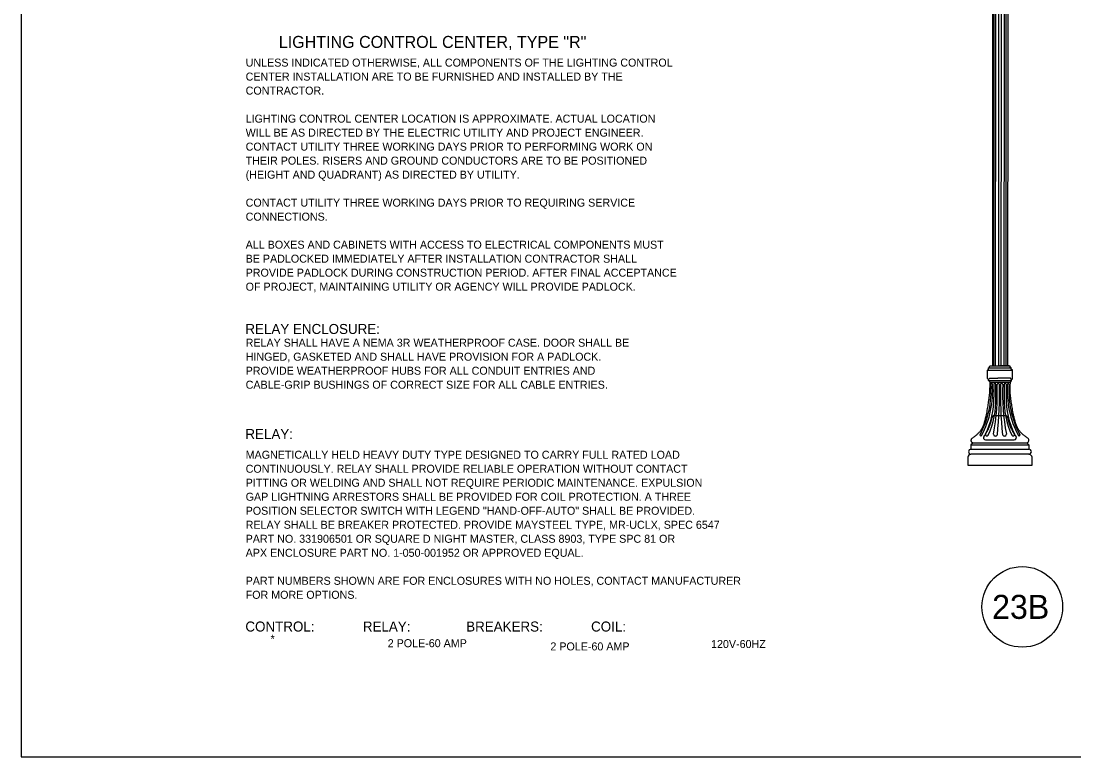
# Model space of a CAD drawing. Extents: x 99968 to 128667, y 90163 to 102182.
# Drawn here: x 120414 to 121992, y 90163 to 91267 of the extents above; entities that cross this region are included whole.
import ezdxf

# ---------------------------------------------------------------- set-up
doc = ezdxf.new("R2010")
doc.units = 0
for name, color, linetype in [('Border Organizer Shape', 7, 'Continuous'), ('Border Prelim Stamp', 7, 'Continuous'), ('RD Standard Plans Active', 7, 'Continuous')]:
    doc.layers.add(name, color=color, linetype=linetype)

msp = doc.modelspace()

# ---------------------------------------------------------------- linework, layer by layer
at = {"layer": 'Border Organizer Shape'}
msp.add_lwpolyline([(120413.5, 90163.3), (123613.2, 90163.3), (123613.2, 92362.9), (120413.5, 92362.9)], close=True, dxfattribs=at)
at = {"layer": 'Border Prelim Stamp'}
msp.add_ellipse((121914.7, 90388.3), major_axis=(-60.5, 0), ratio=0.999984, dxfattribs=at)
at = {"layer": 'RD Standard Plans Active'}
for p, q in [((121870.2, 91544.2), (121869.9, 90749.7)), ((121872.3, 90749.7), (121872.5, 91544.2)), ((121874.8, 90749.7), (121875.1, 91544.2)), ((121879.4, 90749.7), (121879.7, 91544.2)), ((121883.2, 90749.7), (121883.5, 91544.2)), ((121887.8, 90749.7), (121888.1, 91544.2)), ((121890.4, 90749.7), (121890.6, 91544.2)), ((121893, 91544.2), (121892.7, 90749.7)), ((121862.8, 90743.3), (121864.3, 90744.9)), ((121862.8, 90730.8), (121862.8, 90743.3)), ((121862.8, 90743.3), (121899.9, 90743.3)), ((121864.3, 90746.7), (121865.8, 90747.8)), ((121864.3, 90746.7), (121898.1, 90746.7)), ((121864.3, 90744.9), (121864.3, 90746.7)), ((121865.8, 90748.7), (121866.7, 90749.7)), ((121865.8, 90747.8), (121865.8, 90748.7)), ((121866.7, 90749.7), (121895.9, 90749.7)), ((121867.3, 90749.7), (121881.3, 90749.7)), ((121867.9, 90749.7), (121881.3, 90749.7)), ((121867.9, 90749.7), (121894.7, 90749.7)), ((121895.3, 90749.7), (121881.3, 90749.7)), ((121894.7, 90749.7), (121881.3, 90749.7)), ((121896.8, 90748.7), (121895.9, 90749.7)), ((121896.8, 90747.8), (121896.8, 90748.7)), ((121898.3, 90746.5), (121896.8, 90747.8)), ((121898.3, 90744.8), (121898.3, 90746.5)), ((121899.9, 90743.3), (121898.3, 90744.8)), ((121899.9, 90730.4), (121899.9, 90743.3)), ((121864.2, 90729.2), (121862.8, 90730.8)), ((121864.2, 90729.2), (121866.1, 90731.2)), ((121864.2, 90727.6), (121864.2, 90729.2)), ((121866.5, 90725), (121864.2, 90727.6)), ((121864.2, 90727.6), (121899.1, 90727.5)), ((121866.1, 90731.2), (121878, 90731.2)), ((121866.5, 90725), (121896.9, 90725)), ((121897.2, 90731.2), (121878, 90731.2)), ((121896.9, 90725), (121898.7, 90727.1)), ((121898.7, 90729.2), (121897.2, 90731.2)), ((121898.7, 90729.2), (121899.9, 90730.4)), ((121898.7, 90727.1), (121898.7, 90729.2)), ((121871.9, 90722.2), (121872, 90702.5)), ((121874.8, 90722.2), (121874.8, 90702.5)), ((121887.7, 90722.2), (121887.6, 90702.5)), ((121890.5, 90722.2), (121890.5, 90702.5)), ((121890.8, 90674.6), (121871.7, 90674.7)), ((121840.9, 90634.1), (121837.8, 90631.1)), ((121837.8, 90631.1), (121924.7, 90631.1)), ((121837.8, 90631.1), (121837.8, 90624.9)), ((121840.9, 90634.1), (121921.5, 90634.1)), ((121859.5, 90638.9), (121902.6, 90638.9)), ((121888, 90644.5), (121888.2, 90644.5)), ((121921.6, 90634.1), (121924.7, 90631.1)), ((121924.7, 90631.1), (121924.7, 90624.9)), ((121837.8, 90624.9), (121924.7, 90624.9)), ((121924.9, 90617.1), (121837.8, 90617.2)), ((121833, 90612.8), (121833, 90600.8)), ((121833, 90600.8), (121929.5, 90600.7)), ((121929.5, 90600.7), (121929.5, 90612.8))]:
    msp.add_line(p, q, dxfattribs=at)
for centre, radius, start, end in [((121728.1, 90712.3), 139.9, 331.8197, 4.0818), ((121728.1, 90712.3), 142.3, 331.8305, 4.0829), ((121868.8, 90722.2), 1.2, 10.1917, 178.1042), ((121565, 90706.8), 312.3, 349.0347, 2.7955), ((121873.4, 90721.9), 1.47, 12.4479, 167.5521), ((121878.6, 90721.6), 1.74, 17.4755, 167.8586), ((121349.8, 90705.3), 530.8, 353.631, 1.8223), ((122412.7, 90705.3), 530.8, 178.1777, 186.369), ((121883.8, 90721.6), 1.74, 12.1414, 162.5245), ((122197.5, 90706.8), 312.3, 177.2045, 190.9653), ((121889.1, 90721.9), 1.47, 12.4479, 167.5521), ((122034.4, 90712.3), 142.3, 175.9171, 208.1695), ((121893.6, 90722.2), 1.2, 1.8958, 169.8083), ((122034.4, 90712.3), 139.9, 175.9182, 208.1803), ((121755.9, 90699.8), 116.1, 333.1881, 1.3569), ((121754.4, 90697), 120.6, 334.8298, 2.6364), ((122008.1, 90697), 120.6, 177.3636, 205.1702), ((122006.6, 90699.8), 116.1, 178.6431, 206.8119), ((121872.6, 90671.6), 3.13, 105.9115, 168.6516), ((121889.9, 90671.6), 3.13, 11.3484, 73.5955), ((121852.5, 90645.7), 1.2, 149.4961, 332.9376), ((121861.5, 90646.6), 2.18, 159.8381, 335.6064), ((121874.5, 90647.4), 2.93, 180.7471, 344.2322), ((121888, 90647.4), 2.93, 195.7678, 359.2529), ((121900.9, 90646.6), 2.18, 204.3936, 20.1619), ((121910, 90645.7), 1.2, 207.0624, 30.5039), ((121841.6, 90637.9), 3.82, 122.6482, 249.0144), ((121841.6, 90637.9), 3.82, 122.6482, 258.7743), ((121859.6, 90642.1), 3.21, 133.459, 273.3046), ((121902.8, 90642.1), 3.22, 266.7587, 46.6043), ((121920.9, 90637.9), 3.82, 281.2257, 57.3518), ((121838.4, 90611.7), 5.47, 96.0158, 168.122), ((121838.1, 90621), 3.91, 94.6173, 265.3827), ((121838.1, 90621), 3.91, 94.6173, 265.3827), ((121924.4, 90621), 3.91, 274.6173, 85.3827), ((121924.1, 90611.7), 5.47, 11.878, 83.9842)]:
    msp.add_arc(centre, radius, start, end, dxfattribs=at)
for points, degree in [([(121839.6, 90641.1), (121852.5, 90649.7), (121860.2, 90670.2), (121864.9, 90699.6), (121866.3, 90711.2), (121866.5, 90725)], 2), ([(121922.9, 90641.1), (121910, 90649.7), (121902.3, 90670.2), (121897.6, 90699.6), (121896.2, 90711.2), (121896.9, 90725)], 2), ([(121857.4, 90644.4), (121857.7, 90644.8), (121858, 90645.2), (121859.2, 90646.7), (121859.9, 90647.8), (121861.4, 90650.1), (121862, 90651.2), (121863.2, 90653.5), (121863.8, 90654.6), (121864.8, 90656.9), (121865.2, 90658), (121866.1, 90660.2), (121866.4, 90661.2), (121867.1, 90663.4), (121867.4, 90664.4), (121867.9, 90666), (121868, 90666.5), (121868.2, 90667.2), (121868.3, 90667.5), (121868.4, 90668), (121868.8, 90669.2), (121869.1, 90670.5), (121869.4, 90671.7), (121869.5, 90672), (121869.5, 90672.3)], 3), ([(121905.6, 90643.8), (121905.1, 90644.4), (121904.6, 90645), (121903.3, 90646.7), (121902.5, 90647.8), (121901.1, 90650.1), (121900.4, 90651.2), (121899.2, 90653.5), (121898.7, 90654.6), (121897.7, 90656.9), (121897.2, 90658), (121896.4, 90660.2), (121896, 90661.2), (121895.3, 90663.4), (121895, 90664.4), (121894.6, 90666), (121894.4, 90666.5), (121894.2, 90667.2), (121894.2, 90667.5), (121894, 90668), (121893.7, 90669.2), (121893.4, 90670.5), (121893.1, 90671.7), (121893, 90672), (121893, 90672.3)], 3)]:
    msp.add_open_spline(points, degree=degree, dxfattribs=at)

# ---------------------------------------------------------------- texts
at = {"layer": 'Border Prelim Stamp'}
msp.add_text('23B', height=36, dxfattribs=at).set_placement((121869.5, 90370.3))
at = {"layer": 'RD Standard Plans Active'}
for s, height, p in [('LIGHTING CONTROL CENTER, TYPE "R"', 18, (120800, 91226.4)), ('UNLESS INDICATED OTHERWISE, ALL COMPONENTS OF THE LIGHTING CONTROL', 12, (120750.3, 91198.4)), ('CENTER INSTALLATION ARE TO BE FURNISHED AND INSTALLED BY THE', 12, (120750.3, 91177.4)), ('CONTRACTOR.', 12, (120750.3, 91156.4)), ('LIGHTING CONTROL CENTER LOCATION IS APPROXIMATE. ACTUAL LOCATION', 12, (120750.3, 91114.4)), ('WILL BE AS DIRECTED BY THE ELECTRIC UTILITY AND PROJECT ENGINEER.', 12, (120750.3, 91093.4)), ('CONTACT UTILITY THREE WORKING DAYS PRIOR TO PERFORMING WORK ON', 12, (120750.3, 91072.4)), ('THEIR POLES. RISERS AND GROUND CONDUCTORS ARE TO BE POSITIONED', 12, (120750.3, 91051.4)), ('(HEIGHT AND QUADRANT) AS DIRECTED BY UTILITY.', 12, (120750.3, 91030.4)), ('CONTACT UTILITY THREE WORKING DAYS PRIOR TO REQUIRING SERVICE', 12, (120750.3, 90988.4)), ('CONNECTIONS.', 12, (120750.3, 90967.4)), ('ALL BOXES AND CABINETS WITH ACCESS TO ELECTRICAL COMPONENTS MUST', 12, (120750.3, 90925.4)), ('BE PADLOCKED IMMEDIATELY AFTER INSTALLATION CONTRACTOR SHALL', 12, (120750.3, 90904.4)), ('PROVIDE PADLOCK DURING CONSTRUCTION PERIOD. AFTER FINAL ACCEPTANCE', 12, (120750.3, 90883.4)), ('OF PROJECT, MAINTAINING UTILITY OR AGENCY WILL PROVIDE PADLOCK.', 12, (120750.3, 90862.4)), ('RELAY ENCLOSURE:', 15, (120749.9, 90797.5)), ('RELAY SHALL HAVE A NEMA 3R WEATHERPROOF CASE. DOOR SHALL BE', 12, (120750.3, 90778.4)), ('HINGED, GASKETED AND SHALL HAVE PROVISION FOR A PADLOCK.', 12, (120750.3, 90757.4)), ('PROVIDE WEATHERPROOF HUBS FOR ALL CONDUIT ENTRIES AND', 12, (120750.3, 90736.4)), ('CABLE-GRIP BUSHINGS OF CORRECT SIZE FOR ALL CABLE ENTRIES.', 12, (120750.3, 90715.4)), ('RELAY:', 15, (120749.9, 90640)), ('MAGNETICALLY HELD HEAVY DUTY TYPE DESIGNED TO CARRY FULL RATED LOAD ', 12, (120750.3, 90610.4)), ('CONTINUOUSLY. RELAY SHALL PROVIDE RELIABLE OPERATION WITHOUT CONTACT ', 12, (120750.3, 90589.4)), ('PITTING OR WELDING AND SHALL NOT REQUIRE PERIODIC MAINTENANCE. EXPULSION ', 12, (120750.3, 90568.4)), ('GAP LIGHTNING ARRESTORS SHALL BE PROVIDED FOR COIL PROTECTION. A THREE ', 12, (120750.3, 90547.4)), ('POSITION SELECTOR SWITCH WITH LEGEND "HAND-OFF-AUTO" SHALL BE PROVIDED.  ', 12, (120750.3, 90526.4)), ('RELAY SHALL BE BREAKER PROTECTED. PROVIDE MAYSTEEL TYPE, MR-UCLX, SPEC 6547 ', 12, (120750.3, 90505.4)), ('PART NO. 331906501 OR SQUARE D NIGHT MASTER, CLASS 8903, TYPE SPC 81 OR', 12, (120750.3, 90484.4)), ('APX ENCLOSURE PART NO. 1-050-001952 OR APPROVED EQUAL.', 12, (120750.3, 90463.4)), ('PART NUMBERS SHOWN ARE FOR ENCLOSURES WITH NO HOLES, CONTACT MANUFACTURER', 12, (120750.3, 90421.4)), ('FOR MORE OPTIONS.  ', 12, (120750.3, 90400.4)), ('CONTROL:             RELAY:               BREAKERS:             COIL:', 15, (120749.9, 90351.3)), ('*', 12, (120787.7, 90334.4)), ('2 POLE-60 AMP', 12, (120963.3, 90327.8)), ('2 POLE-60 AMP', 12, (121207.2, 90323)), ('120V-60HZ', 12, (121448.1, 90326.6))]:
    msp.add_text(s, height=height, dxfattribs=at).set_placement(p)

doc.saveas('drawing.dxf')
